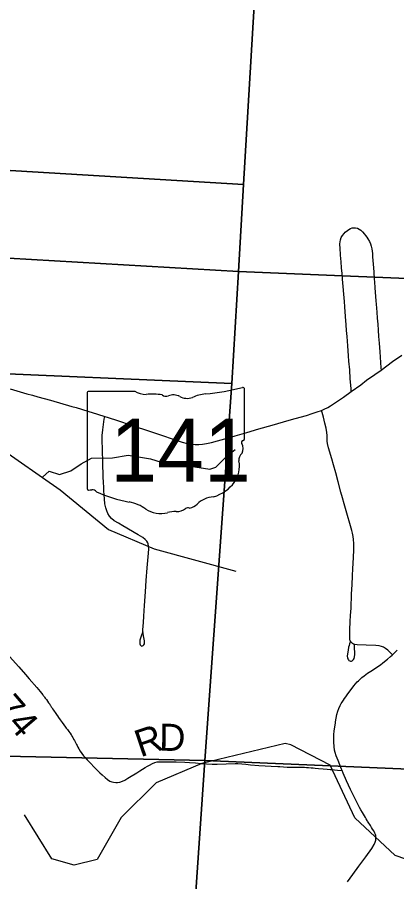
# Model space of a CAD drawing. Extents: x 21.4 to 65.3, y 4 to 26.
# Drawn here: x 25.016 to 25.81, y 22.248 to 24.062 of the extents above; entities that cross this region are included whole.
import ezdxf

# ---------------------------------------------------------------- set-up
doc = ezdxf.new("R2010")
doc.units = 0
for name, color, linetype in [('GM_X_County_Road', 7, 'Continuous'), ('GM_X_Minor_River', 7, 'Continuous'), ('GM_X_Section', 7, 'Continuous'), ('GM_X_State_Location', 7, 'Continuous'), ('GM_X_State_Route', 7, 'Continuous'), ('GM_X_State_Shield', 7, 'Continuous'), ('GM_X_Township_Road', 7, 'Continuous'), ('GM_X_Township_Road_Text', 7, 'Continuous')]:
    doc.layers.add(name, color=color, linetype=linetype)

msp = doc.modelspace()

# ---------------------------------------------------------------- linework, layer by layer
at = {"layer": 'GM_X_County_Road'}
for points in [[(25.7005, 23.041), (25.6969, 23.0535), (25.6937, 23.0653), (25.6877, 23.0873), (25.6826, 23.1062), (25.678, 23.123), (25.6746, 23.1355), (25.6679, 23.1588), (25.6657, 23.1673), (25.6648, 23.1722), (25.6645, 23.176), (25.6647, 23.1799), (25.6649, 23.1841), (25.6643, 23.1907), (25.6626, 23.1998), (25.66, 23.2106), (25.6569, 23.2228), (25.6543, 23.2327), (25.6529, 23.2372)], [(25.8016, 22.7243), (25.7965, 22.7292), (25.7916, 22.7339), (25.7867, 22.7375), (25.7825, 22.74), (25.7786, 22.7415), (25.7739, 22.7427), (25.7666, 22.7435), (25.7468, 22.7445), (25.7275, 22.7452), (25.7231, 22.7458), (25.7224, 22.746), (25.72, 22.7468), (25.7176, 22.748), (25.7156, 22.7498), (25.7143, 22.7514), (25.7135, 22.753), (25.7132, 22.7538), (25.7124, 22.757), (25.7121, 22.7633), (25.7126, 22.7764), (25.7133, 22.7938), (25.7139, 22.8068), (25.7148, 22.8223), (25.716, 22.8515), (25.717, 22.872), (25.7179, 22.8893), (25.7189, 22.9061), (25.7193, 22.9154), (25.7208, 22.9439), (25.7208, 22.9575), (25.7203, 22.9661), (25.7193, 22.9727), (25.7176, 22.9795), (25.7162, 22.9853), (25.7033, 23.0314), (25.7005, 23.041)], [(25.6825, 22.5833), (25.6852, 22.5986), (25.6869, 22.6059), (25.6889, 22.6112), (25.6922, 22.618), (25.6942, 22.6218), (25.6961, 22.6249), (25.6987, 22.6288), (25.7013, 22.6327), (25.7036, 22.636), (25.7066, 22.6401), (25.7122, 22.6477), (25.7169, 22.6542), (25.7208, 22.6594), (25.7244, 22.6636), (25.7277, 22.6672), (25.7302, 22.6699), (25.7344, 22.6739), (25.7377, 22.6765), (25.7425, 22.6803), (25.7495, 22.6854), (25.7598, 22.6921), (25.7773, 22.7042), (25.7806, 22.7068), (25.785, 22.7102), (25.7912, 22.7152), (25.7973, 22.7204), (25.8009, 22.7237), (25.8016, 22.7243), (25.8118, 22.7338)], [(25.7072, 22.2481), (25.7183, 22.2629), (25.7311, 22.2806), (25.7458, 22.3002), (25.7585, 22.3174), (25.7632, 22.3258), (25.7656, 22.331), (25.7666, 22.3353), (25.7669, 22.3393), (25.7669, 22.3427), (25.7666, 22.3453), (25.766, 22.3468), (25.7649, 22.3499), (25.7625, 22.3546), (25.76, 22.3584), (25.7577, 22.3619), (25.7554, 22.3657), (25.7509, 22.373), (25.7496, 22.3752), (25.7486, 22.3767), (25.7467, 22.3799), (25.745, 22.3826), (25.7387, 22.3931), (25.7354, 22.3986), (25.7327, 22.4036), (25.7295, 22.4095), (25.7205, 22.4273), (25.7138, 22.4413), (25.7053, 22.4599), (25.6983, 22.4759), (25.696, 22.4815), (25.6948, 22.4845), (25.6877, 22.5024), (25.6838, 22.5122), (25.6813, 22.5193), (25.6802, 22.5242), (25.6792, 22.5317), (25.6789, 22.5411), (25.6791, 22.5573), (25.6796, 22.5642), (25.6821, 22.5814), (25.6825, 22.5833)]]:
    msp.add_lwpolyline(points, dxfattribs=at)
at = {"layer": 'GM_X_Minor_River'}
for points in [[(24.9284, 23.1936), (25.1054, 23.0707), (25.2067, 22.9874), (25.3021, 22.9465), (25.4732, 22.8994)], [(25.0682, 23.0967), (25.0824, 23.1096), (25.104, 23.1024), (25.1275, 23.1104), (25.1495, 23.1252), (25.1711, 23.137), (25.2147, 23.1378), (25.248, 23.1432), (25.2943, 23.1356), (25.317, 23.1281), (25.3473, 23.1247), (25.4186, 23.1137), (25.4315, 23.1179), (25.4542, 23.1408), (25.4721, 23.1548)], [(26.2211, 22.2005), (26.18, 22.2654), (26.0743, 22.2834), (25.8903, 22.2746), (25.8075, 22.3031), (25.723, 22.382), (25.6714, 22.4928), (25.5885, 22.5353), (25.5766, 22.5382), (25.4022, 22.4961), (25.3063, 22.4557), (25.2332, 22.3826), (25.1828, 22.2945), (25.1347, 22.283), (25.0875, 22.2959), (25.0308, 22.3887)]]:
    msp.add_lwpolyline(points, dxfattribs=at)
at = {"layer": 'GM_X_Section'}
for points in [[(26.5825, 24.5101), (26.5198, 23.4854), (25.4788, 23.5287), (25.4893, 23.7114), (25.5145, 24.1345), (25.5389, 24.555)], [(25.5145, 24.1345), (25.4893, 23.7114), (24.4301, 23.7749), (24.457, 24.1912)], [(24.4301, 23.7749), (25.4893, 23.7114), (25.4788, 23.5287), (24.4178, 23.5899)], [(24.4175, 23.5863), (24.4178, 23.5899), (25.4788, 23.5287), (25.4647, 23.2936), (24.8812, 23.3189), (24.4019, 23.3397)], [(25.4788, 23.5287), (26.5198, 23.4854), (26.5078, 23.2694), (26.4931, 23.0203), (26.4742, 22.7032), (26.4597, 22.4573), (25.4085, 22.5025), (25.4647, 23.2936)], [(25.4647, 23.2936), (25.4085, 22.5025), (24.828, 22.5152), (24.8812, 23.3189)], [(24.3505, 22.5376), (24.828, 22.5152), (25.4085, 22.5025), (25.3384, 21.4821), (24.7985, 21.5074), (24.2858, 21.5075), (24.3136, 21.9252), (24.3404, 22.3383)], [(25.4085, 22.5025), (26.4597, 22.4573), (26.4491, 22.292), (26.4111, 21.6607), (26.3977, 21.4352), (25.3384, 21.4821)]]:
    msp.add_lwpolyline(points, close=True, dxfattribs=at)
at = {"layer": 'GM_X_State_Route'}
msp.add_lwpolyline([(25.0006, 23.282), (25.0358, 23.2719), (25.0471, 23.2687), (25.0585, 23.2655), (25.0854, 23.2582), (25.1301, 23.2453), (25.1385, 23.2429), (25.1634, 23.2354), (25.1837, 23.2293), (25.1986, 23.2246), (25.2056, 23.2225), (25.2251, 23.2159), (25.2544, 23.2062), (25.2949, 23.1926), (25.3114, 23.1869), (25.3485, 23.1743), (25.361, 23.1705), (25.3713, 23.1679), (25.3799, 23.1665), (25.388, 23.1658), (25.3962, 23.1657), (25.4037, 23.1662), (25.4118, 23.1675), (25.4227, 23.1699), (25.4551, 23.179), (25.4718, 23.1838), (25.4963, 23.1908), (25.5219, 23.1982), (25.5494, 23.2059), (25.5733, 23.2128), (25.5855, 23.2163), (25.5978, 23.2198), (25.6212, 23.2265), (25.6336, 23.2304), (25.6439, 23.2338), (25.6529, 23.2372), (25.6586, 23.2397), (25.6659, 23.2434), (25.6721, 23.2468), (25.6781, 23.2506), (25.6907, 23.259), (25.6993, 23.2651), (25.7154, 23.2768), (25.735, 23.291), (25.7475, 23.3002), (25.7647, 23.3124), (25.7777, 23.3217), (25.8018, 23.3394), (25.8212, 23.353)], dxfattribs=at)
at = {"layer": 'GM_X_State_Shield'}
for p, q in [((25.1619, 23.2736), (25.1619, 23.0735)), ((25.2617, 23.277), (25.1651, 23.277)), ((25.4915, 23.1773), (25.4915, 23.282)), ((25.4914, 23.1773), (25.4915, 23.1773))]:
    msp.add_line(p, q, dxfattribs=at)
for centre, major_axis, start_param, end_param in [((25.1657, 23.274), (0.00382, 0), 1.712693, 3.28349), ((25.2846, 23.3003), (0.037, 0), 4.042523, 4.731795), ((25.3741, 23.5499), (0.3495, 0), 4.814394, 5.042369), ((25.4878, 23.2824), (0.00367, 0), 6.141152, 7.989035), ((25.2969, 23.1647), (0.133, 0), 1.404758, 1.657858), ((25.3271, 23.2751), (0.0107, 0), 3.836095, 5.185415), ((25.3428, 23.2519), (0.0222, 0), 0.950623, 2.079405), ((25.3715, 23.2837), (0.0267, 0), 4.081561, 5.145723), ((25.4187, 23.2159), (0.0703, 0), 1.699011, 2.107814), ((25.4906, 23.1696), (0.00568, 0), 1.883978, 3.671073), ((25.4545, 23.1564), (0.0341, 0), 5.934695, 6.695948), ((25.4876, 23.1769), (0.00393, 0), 5.05454, 6.418171), ((25.5046, 23.1335), (0.0248, 0), 2.387724, 3.262537), ((25.3937, 23.1202), (0.0874, 0), 5.101752, 6.440018), ((25.1657, 23.073), (0.00385, 0), 3.00124, 4.508301), ((25.1663, 23.0935), (0.0294, 0), 4.665946, 4.897461), ((25.1723, 23.0619), (0.0106, 0), 0.519207, 1.627899), ((25.3061, 23.2417), (0.2524, 0), 4.195997, 4.488961), ((25.4305, 23.0173), (0.0479, 0), 1.647645, 2.488434), ((25.2309, 22.9836), (0.079, 0), 0.823519, 1.323587), ((25.3699, 23.0541), (0.0282, 0), 4.937069, 5.64225), ((25.3163, 23.0609), (0.0501, 0), 4.026481, 4.996735), ((25.3452, 22.9918), (0.0412, 0), 1.495662, 1.94098), ((25.3489, 23.046), (0.0267, 0), 4.691044, 5.507374), ((25.3731, 23.0266), (0.00752, 0), 1.147584, 2.315152)]:
    msp.add_ellipse(centre, major_axis=major_axis, ratio=0.8, start_param=start_param, end_param=end_param, dxfattribs=at)
at = {"layer": 'GM_X_Township_Road'}
for points in [[(25.7154, 23.2768), (25.7149, 23.2827), (25.7133, 23.3034), (25.712, 23.3222), (25.7105, 23.3405), (25.7096, 23.3519), (25.708, 23.3726), (25.7066, 23.392), (25.7056, 23.4045), (25.7047, 23.4163), (25.703, 23.4342), (25.7017, 23.4541), (25.7008, 23.4656), (25.6968, 23.5123), (25.6959, 23.524), (25.695, 23.5364), (25.6939, 23.5487), (25.6927, 23.5628), (25.6917, 23.5782), (25.6914, 23.5844), (25.6914, 23.5869), (25.6917, 23.5907), (25.6926, 23.5951), (25.6943, 23.5999), (25.6969, 23.6043), (25.7001, 23.6083), (25.7028, 23.611), (25.7071, 23.6146), (25.7102, 23.6168), (25.7136, 23.6186), (25.7173, 23.6199), (25.7211, 23.6204), (25.7244, 23.6203), (25.7281, 23.6193), (25.7316, 23.6177), (25.7353, 23.6152), (25.739, 23.6118), (25.7432, 23.6071), (25.7454, 23.604), (25.7479, 23.6005), (25.7503, 23.5969), (25.7534, 23.5916), (25.7556, 23.5864), (25.7571, 23.5817), (25.7583, 23.5762), (25.7589, 23.5713), (25.7596, 23.5663), (25.7601, 23.5598), (25.7607, 23.5512), (25.7612, 23.5446), (25.7624, 23.5272), (25.7635, 23.5124), (25.7639, 23.5068), (25.7648, 23.4945), (25.766, 23.4762), (25.7669, 23.4673), (25.7676, 23.4597), (25.7683, 23.4514), (25.769, 23.443), (25.7699, 23.4307), (25.7708, 23.4177), (25.7717, 23.4054), (25.7726, 23.3919), (25.7735, 23.3785), (25.7748, 23.3601), (25.7774, 23.3264), (25.7777, 23.3217)], [(25.1938, 23.1548), (25.1938, 23.1558), (25.1934, 23.1738), (25.1936, 23.1842), (25.1945, 23.196), (25.1958, 23.2072), (25.1976, 23.2188), (25.1986, 23.2246)], [(25.2782, 22.7722), (25.2755, 22.7655), (25.274, 22.7612), (25.2724, 22.7546), (25.272, 22.7503), (25.2722, 22.7472), (25.273, 22.7448), (25.2742, 22.7434), (25.2757, 22.7426), (25.2776, 22.7429), (25.2795, 22.7438), (25.2807, 22.7452), (25.2817, 22.7475), (25.2821, 22.7499), (25.282, 22.7536), (25.2805, 22.7608), (25.2782, 22.7722), (25.2782, 22.7765), (25.2799, 22.7919), (25.2808, 22.8055), (25.2821, 22.8278), (25.2839, 22.8563), (25.2857, 22.8798), (25.2876, 22.907), (25.289, 22.9221), (25.2902, 22.9373), (25.2909, 22.9466), (25.2907, 22.9522), (25.2896, 22.957), (25.2887, 22.9593), (25.2869, 22.9625), (25.2836, 22.9663), (25.2787, 22.9701), (25.2691, 22.9759), (25.2369, 22.9947), (25.2272, 23.0003), (25.2187, 23.0054), (25.2128, 23.01), (25.2084, 23.0151), (25.2049, 23.021), (25.2028, 23.0261), (25.2008, 23.0327), (25.1991, 23.0412), (25.1979, 23.0517), (25.1969, 23.0684), (25.1965, 23.0764), (25.1962, 23.0851), (25.1957, 23.0981), (25.1948, 23.1272), (25.1945, 23.1359), (25.1941, 23.1458), (25.1938, 23.1548)], [(25.7135, 22.753), (25.7116, 22.747), (25.7106, 22.7437), (25.7097, 22.7401), (25.7087, 22.7342), (25.7074, 22.726), (25.7069, 22.7211), (25.7072, 22.718), (25.7079, 22.7156), (25.7092, 22.7135), (25.7105, 22.7122), (25.7121, 22.7113), (25.7139, 22.7108), (25.7157, 22.7109), (25.7175, 22.7116), (25.7189, 22.7127), (25.7201, 22.7142), (25.7211, 22.7164), (25.722, 22.72), (25.7225, 22.7249), (25.7226, 22.7311), (25.7223, 22.7361), (25.7223, 22.7396), (25.7224, 22.746)], [(24.9993, 22.7209), (25.0185, 22.6989), (25.0324, 22.6831), (25.0404, 22.6736), (25.0561, 22.6553), (25.0632, 22.6469), (25.0687, 22.6402), (25.0698, 22.6388), (25.0718, 22.6364), (25.0725, 22.6354), (25.074, 22.6335), (25.0748, 22.6325), (25.0766, 22.6301), (25.0791, 22.6266), (25.0811, 22.6236), (25.0828, 22.6212), (25.0835, 22.6203), (25.0845, 22.6187), (25.0851, 22.6177), (25.0858, 22.6167), (25.0867, 22.6152), (25.0877, 22.6136), (25.0894, 22.6111), (25.0914, 22.608), (25.0962, 22.6008), (25.0989, 22.5968), (25.0995, 22.5959), (25.1016, 22.5929), (25.1053, 22.5879), (25.1075, 22.5849), (25.1097, 22.5819), (25.1167, 22.5725), (25.1182, 22.5706), (25.1204, 22.5676), (25.1236, 22.5632), (25.1253, 22.5608), (25.126, 22.5598), (25.1283, 22.5563), (25.1289, 22.5553), (25.1299, 22.5538), (25.1317, 22.5507), (25.1325, 22.5492), (25.1335, 22.5474), (25.135, 22.5447), (25.1367, 22.5415), (25.1395, 22.536), (25.1406, 22.5338), (25.1423, 22.5304), (25.1443, 22.5266), (25.1471, 22.5218), (25.1507, 22.5168), (25.1541, 22.5124), (25.1575, 22.5088), (25.1616, 22.5041), (25.1637, 22.5019), (25.168, 22.4974), (25.1776, 22.4877), (25.1885, 22.4767), (25.193, 22.4724), (25.1994, 22.4665), (25.2048, 22.4623), (25.2096, 22.4593), (25.2137, 22.4576), (25.2173, 22.4566), (25.2217, 22.456), (25.2255, 22.4562), (25.2305, 22.4571), (25.2359, 22.4589), (25.241, 22.4613), (25.2474, 22.4652), (25.2506, 22.4671), (25.2659, 22.4764), (25.2722, 22.4804), (25.2837, 22.4876), (25.288, 22.4902), (25.2923, 22.4926), (25.2988, 22.4961), (25.3039, 22.4981), (25.3087, 22.4993), (25.3128, 22.4998), (25.3206, 22.4998), (25.3256, 22.4998), (25.3299, 22.4997), (25.3349, 22.4996), (25.3485, 22.4994), (25.3664, 22.4987), (25.3763, 22.4981), (25.3887, 22.4973), (25.401, 22.4964), (25.4122, 22.4953), (25.4239, 22.4946), (25.4345, 22.4947), (25.4718, 22.4958), (25.4773, 22.4959), (25.486, 22.4955), (25.4946, 22.4945), (25.5044, 22.4934), (25.5217, 22.4919), (25.5347, 22.491), (25.5472, 22.4903), (25.5614, 22.4898), (25.5656, 22.4895), (25.581, 22.4887), (25.5983, 22.4882), (25.6028, 22.4884), (25.6076, 22.4882), (25.6138, 22.4883), (25.6175, 22.4883), (25.6217, 22.488), (25.6259, 22.4875), (25.6313, 22.4873), (25.6357, 22.4868), (25.6399, 22.4863), (25.6467, 22.4856), (25.6566, 22.4847), (25.6646, 22.484), (25.6708, 22.4835), (25.6751, 22.4832), (25.6799, 22.4828), (25.6862, 22.4823), (25.696, 22.4815)]]:
    msp.add_lwpolyline(points, dxfattribs=at)

# ---------------------------------------------------------------- texts
at = {"layer": 'GM_X_State_Location'}
msp.add_text('141', height=0.000189, rotation=0, dxfattribs=at).set_placement((25.2561, 23.1465))
for s in ['s', 'r']:
    msp.add_text(s, height=0.000189, dxfattribs=at).set_placement((25.323, 23.1602))
at = {"layer": 'GM_X_State_Shield'}
msp.add_text('141', height=0.13184, dxfattribs=at).set_placement((25.2105, 23.0876))
at = {"layer": 'GM_X_Township_Road_Text'}
for s, height, rotation, p in [('T-374', 0.05682, 310.6916, (24.8914, 22.6969)), ('R', 0.0568, 18.7052, (25.2734, 22.5087)), ('D', 0.0568, 359.3188, (25.3126, 22.5229))]:
    msp.add_text(s, height=height, rotation=rotation, dxfattribs=at).set_placement(p)

doc.saveas('drawing.dxf')
